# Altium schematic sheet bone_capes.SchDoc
size A4
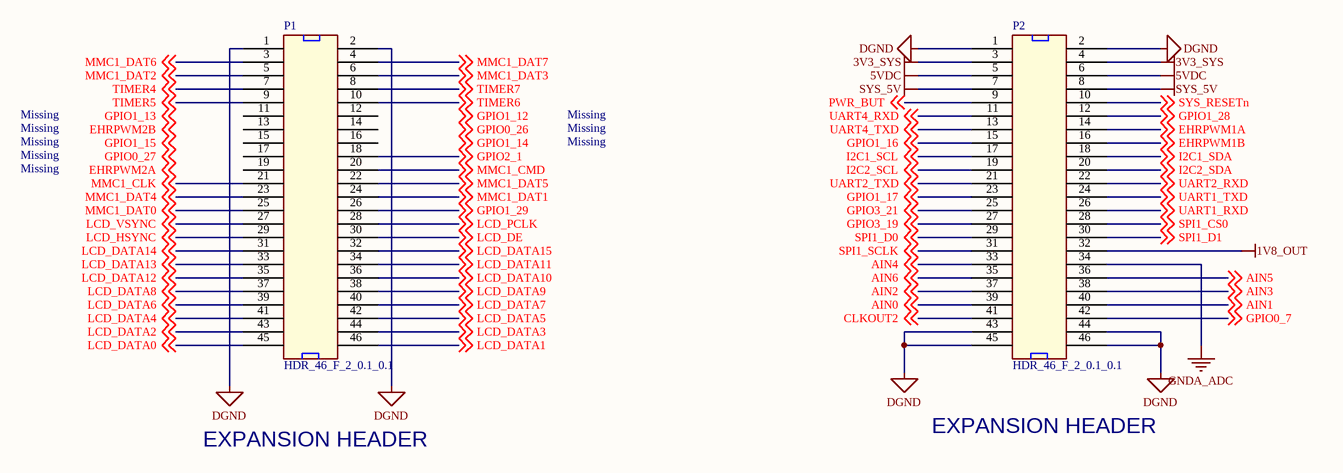
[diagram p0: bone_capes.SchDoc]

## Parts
P1  HDR_46_F_2_0.1_0.1  [DIP46]
P2  HDR_46_F_2_0.1_0.1  [DIP46]

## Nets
1V8_OUT: P2.32
3V3_SYS: P2.3 P2.4
5VDC: P2.5 P2.6
DGND: P1.1 P1.2 P2.1 P2.2 P2.43 P2.44 P2.45 P2.46
GNDA_ADC: P2.34
SYS_5V: P2.7 P2.8
AIN0: P2.39 ; off-sheet AIN0
AIN1: P2.40 ; off-sheet AIN1
AIN2: P2.37 ; off-sheet AIN2
AIN3: P2.38 ; off-sheet AIN3
AIN4: P2.33 ; off-sheet AIN4
AIN5: P2.36 ; off-sheet AIN5
AIN6: P2.35 ; off-sheet AIN6
CLKOUT2: P2.41 ; off-sheet CLKOUT2
EHRPWM1A: P2.14 ; off-sheet EHRPWM1A
EHRPWM1B: P2.16 ; off-sheet EHRPWM1B
GPIO0_7: P2.42 ; off-sheet GPIO0_7
GPIO1_16: P2.15 ; off-sheet GPIO1_16
GPIO1_17: P2.23 ; off-sheet GPIO1_17
GPIO1_28: P2.12 ; off-sheet GPIO1_28
GPIO1_29: P1.26 ; off-sheet GPIO1_29
GPIO2_1: P1.18 ; off-sheet GPIO2_1
GPIO3_19: P2.27 ; off-sheet GPIO3_19
GPIO3_21: P2.25 ; off-sheet GPIO3_21
I2C1_SCL: P2.17 ; off-sheet I2C1_SCL
I2C1_SDA: P2.18 ; off-sheet I2C1_SDA
I2C2_SCL: P2.19 ; off-sheet I2C2_SCL
I2C2_SDA: P2.20 ; off-sheet I2C2_SDA
LCD_DATA0: P1.45 ; off-sheet LCD_DATA0
LCD_DATA1: P1.46 ; off-sheet LCD_DATA1
LCD_DATA2: P1.43 ; off-sheet LCD_DATA2
LCD_DATA3: P1.44 ; off-sheet LCD_DATA3
LCD_DATA4: P1.41 ; off-sheet LCD_DATA4
LCD_DATA5: P1.42 ; off-sheet LCD_DATA5
LCD_DATA6: P1.39 ; off-sheet LCD_DATA6
LCD_DATA7: P1.40 ; off-sheet LCD_DATA7
LCD_DATA8: P1.37 ; off-sheet LCD_DATA8
LCD_DATA9: P1.38 ; off-sheet LCD_DATA9
LCD_DATA10: P1.36 ; off-sheet LCD_DATA10
LCD_DATA11: P1.34 ; off-sheet LCD_DATA11
LCD_DATA12: P1.35 ; off-sheet LCD_DATA12
LCD_DATA13: P1.33 ; off-sheet LCD_DATA13
LCD_DATA14: P1.31 ; off-sheet LCD_DATA14
LCD_DATA15: P1.32 ; off-sheet LCD_DATA15
LCD_DE: P1.30 ; off-sheet LCD_DE
LCD_HSYNC: P1.29 ; off-sheet LCD_HSYNC
LCD_PCLK: P1.28 ; off-sheet LCD_PCLK
LCD_VSYNC: P1.27 ; off-sheet LCD_VSYNC
MMC1_CLK: P1.21 ; off-sheet MMC1_CLK
MMC1_CMD: P1.20 ; off-sheet MMC1_CMD
MMC1_DAT0: P1.25 ; off-sheet MMC1_DAT0
MMC1_DAT1: P1.24 ; off-sheet MMC1_DAT1
MMC1_DAT2: P1.5 ; off-sheet MMC1_DAT2
MMC1_DAT3: P1.6 ; off-sheet MMC1_DAT3
MMC1_DAT4: P1.23 ; off-sheet MMC1_DAT4
MMC1_DAT5: P1.22 ; off-sheet MMC1_DAT5
MMC1_DAT6: P1.3 ; off-sheet MMC1_DAT6
MMC1_DAT7: P1.4 ; off-sheet MMC1_DAT7
PWR_BUT: P2.9 ; off-sheet PWR_BUT
SPI1_CS0: P2.28 ; off-sheet SPI1_CS0
SPI1_D0: P2.29 ; off-sheet SPI1_D0
SPI1_D1: P2.30 ; off-sheet SPI1_D1
SPI1_SCLK: P2.31 ; off-sheet SPI1_SCLK
SYS_RESETn: P2.10 ; off-sheet SYS_RESETn
TIMER4: P1.7 ; off-sheet TIMER4
TIMER5: P1.9 ; off-sheet TIMER5
TIMER6: P1.10 ; off-sheet TIMER6
TIMER7: P1.8 ; off-sheet TIMER7
UART1_RXD: P2.26 ; off-sheet UART1_RXD
UART1_TXD: P2.24 ; off-sheet UART1_TXD
UART2_RXD: P2.22 ; off-sheet UART2_RXD
UART2_TXD: P2.21 ; off-sheet UART2_TXD
UART4_RXD: P2.11 ; off-sheet UART4_RXD
UART4_TXD: P2.13 ; off-sheet UART4_TXD

Not connected (* = marked no-connect by the designer): P1 11(6) 12(31) 13(7) 14(32) 15(8) 16(33) 17(9) 19(10)

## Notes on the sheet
- Missing
- EXPANSION HEADER
- Labels drawn without touching a wire or pin: EHRPWM2A, EHRPWM2B, GPIO0_26, GPIO0_27, GPIO1_12, GPIO1_13, GPIO1_14, GPIO1_15

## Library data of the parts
P1 P2 = HDR_46_F_2_0.1_0.1: NN HEADER FMAL 46PS.1" DL GOLD; Mfr: major league electronics; P/N: SSHS-123-D-02-GT-LF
